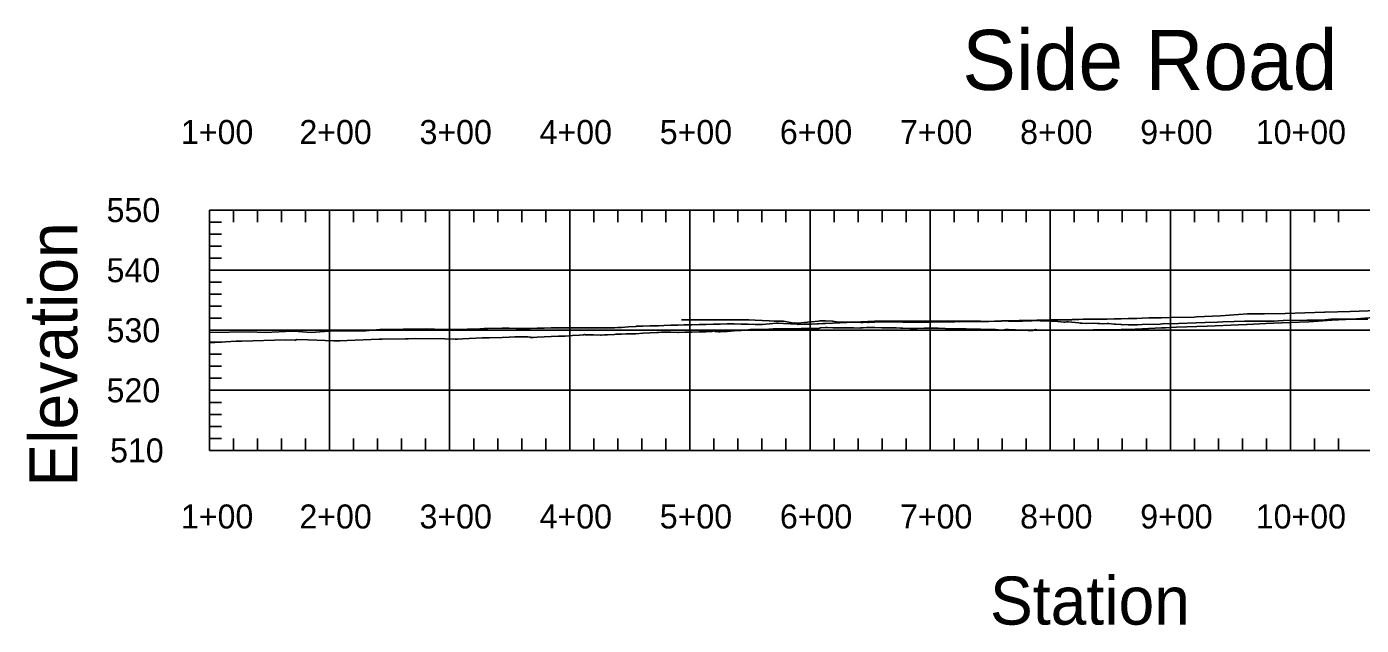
# Model space of a CAD drawing. Extents: x 704797 to 712284, y 374940 to 376945.
# Drawn here: x 708267 to 709378, y 376447 to 376945 of the extents above; entities that cross this region are included whole.
import ezdxf

# ---------------------------------------------------------------- set-up
doc = ezdxf.new("R2010")
doc.units = 0
for name, color, linetype in [('1', 7, 'Continuous'), ('61', 7, 'Continuous'), ('63', 7, 'Continuous'), ('Existing', 7, 'Continuous')]:
    doc.layers.add(name, color=color, linetype=linetype)

msp = doc.modelspace()

# ---------------------------------------------------------------- linework, layer by layer
at = {"layer": '61'}
for p, q in [((708419.5, 376792.3), (709919.5, 376792.3)), ((708419.5, 376592.3), (708419.5, 376792.3)), ((708439.5, 376792.3), (708439.5, 376782.3)), ((708459.5, 376792.3), (708459.5, 376782.3)), ((708479.5, 376792.3), (708479.5, 376782.3)), ((708499.5, 376792.3), (708499.5, 376782.3)), ((708519.5, 376592.3), (708519.5, 376792.3)), ((708539.5, 376792.3), (708539.5, 376782.3)), ((708559.5, 376792.3), (708559.5, 376782.3)), ((708579.5, 376792.3), (708579.5, 376782.3)), ((708599.5, 376792.3), (708599.5, 376782.3)), ((708619.5, 376592.3), (708619.5, 376792.3)), ((708639.5, 376792.3), (708639.5, 376782.3)), ((708659.5, 376792.3), (708659.5, 376782.3)), ((708679.5, 376792.3), (708679.5, 376782.3)), ((708699.5, 376792.3), (708699.5, 376782.3)), ((708719.5, 376592.3), (708719.5, 376792.3)), ((708739.5, 376792.3), (708739.5, 376782.3)), ((708759.5, 376792.3), (708759.5, 376782.3)), ((708779.5, 376792.3), (708779.5, 376782.3)), ((708799.5, 376792.3), (708799.5, 376782.3)), ((708819.5, 376592.3), (708819.5, 376792.3)), ((708839.5, 376792.3), (708839.5, 376782.3)), ((708859.5, 376792.3), (708859.5, 376782.3)), ((708879.5, 376792.3), (708879.5, 376782.3)), ((708899.5, 376792.3), (708899.5, 376782.3)), ((708919.5, 376592.3), (708919.5, 376792.3)), ((708939.5, 376792.3), (708939.5, 376782.3)), ((708959.5, 376792.3), (708959.5, 376782.3)), ((708979.5, 376792.3), (708979.5, 376782.3)), ((708999.5, 376792.3), (708999.5, 376782.3)), ((709019.5, 376592.3), (709019.5, 376792.3)), ((709039.5, 376792.3), (709039.5, 376782.3)), ((709059.5, 376792.3), (709059.5, 376782.3)), ((709079.5, 376792.3), (709079.5, 376782.3)), ((709099.5, 376792.3), (709099.5, 376782.3)), ((709119.5, 376592.3), (709119.5, 376792.3)), ((709139.5, 376792.3), (709139.5, 376782.3)), ((709159.5, 376792.3), (709159.5, 376782.3)), ((709179.5, 376792.3), (709179.5, 376782.3)), ((709199.5, 376792.3), (709199.5, 376782.3)), ((709219.5, 376592.3), (709219.5, 376792.3)), ((709239.5, 376792.3), (709239.5, 376782.3)), ((709259.5, 376792.3), (709259.5, 376782.3)), ((709279.5, 376792.3), (709279.5, 376782.3)), ((709299.5, 376792.3), (709299.5, 376782.3)), ((709319.5, 376592.3), (709319.5, 376792.3)), ((709339.5, 376792.3), (709339.5, 376782.3)), ((709359.5, 376792.3), (709359.5, 376782.3)), ((708419.5, 376782.3), (708429.5, 376782.3)), ((708419.5, 376772.3), (708429.5, 376772.3)), ((708419.5, 376762.3), (708429.5, 376762.3)), ((708419.5, 376752.3), (708429.5, 376752.3)), ((708419.5, 376742.3), (709919.5, 376742.3)), ((708419.5, 376732.3), (708429.5, 376732.3)), ((708419.5, 376722.3), (708429.5, 376722.3)), ((708419.5, 376712.3), (708429.5, 376712.3)), ((708419.5, 376702.3), (708429.5, 376702.3)), ((708419.5, 376692.3), (709919.5, 376692.3)), ((708419.5, 376682.3), (708429.5, 376682.3)), ((708419.5, 376672.3), (708429.5, 376672.3)), ((708419.5, 376662.3), (708429.5, 376662.3)), ((708419.5, 376652.3), (708429.5, 376652.3)), ((708419.5, 376642.3), (709919.5, 376642.3)), ((708419.5, 376632.3), (708429.5, 376632.3)), ((708419.5, 376622.3), (708429.5, 376622.3)), ((708419.5, 376612.3), (708429.5, 376612.3)), ((708419.5, 376602.3), (708429.5, 376602.3)), ((708439.5, 376592.3), (708439.5, 376602.3)), ((708459.5, 376592.3), (708459.5, 376602.3)), ((708479.5, 376592.3), (708479.5, 376602.3)), ((708499.5, 376592.3), (708499.5, 376602.3)), ((708539.5, 376592.3), (708539.5, 376602.3)), ((708559.5, 376592.3), (708559.5, 376602.3)), ((708579.5, 376592.3), (708579.5, 376602.3)), ((708599.5, 376592.3), (708599.5, 376602.3)), ((708639.5, 376592.3), (708639.5, 376602.3)), ((708659.5, 376592.3), (708659.5, 376602.3)), ((708679.5, 376592.3), (708679.5, 376602.3)), ((708699.5, 376592.3), (708699.5, 376602.3)), ((708739.5, 376592.3), (708739.5, 376602.3)), ((708759.5, 376592.3), (708759.5, 376602.3)), ((708779.5, 376592.3), (708779.5, 376602.3)), ((708799.5, 376592.3), (708799.5, 376602.3)), ((708839.5, 376592.3), (708839.5, 376602.3)), ((708859.5, 376592.3), (708859.5, 376602.3)), ((708879.5, 376592.3), (708879.5, 376602.3)), ((708899.5, 376592.3), (708899.5, 376602.3)), ((708939.5, 376592.3), (708939.5, 376602.3)), ((708959.5, 376592.3), (708959.5, 376602.3)), ((708979.5, 376592.3), (708979.5, 376602.3)), ((708999.5, 376592.3), (708999.5, 376602.3)), ((709039.5, 376592.3), (709039.5, 376602.3)), ((709059.5, 376592.3), (709059.5, 376602.3)), ((709079.5, 376592.3), (709079.5, 376602.3)), ((709099.5, 376592.3), (709099.5, 376602.3)), ((709139.5, 376592.3), (709139.5, 376602.3)), ((709159.5, 376592.3), (709159.5, 376602.3)), ((709179.5, 376592.3), (709179.5, 376602.3)), ((709199.5, 376592.3), (709199.5, 376602.3)), ((709239.5, 376592.3), (709239.5, 376602.3)), ((709259.5, 376592.3), (709259.5, 376602.3)), ((709279.5, 376592.3), (709279.5, 376602.3)), ((709299.5, 376592.3), (709299.5, 376602.3)), ((709339.5, 376592.3), (709339.5, 376602.3)), ((709359.5, 376592.3), (709359.5, 376602.3)), ((708419.5, 376592.3), (709919.5, 376592.3))]:
    msp.add_line(p, q, dxfattribs=at)
at = {"layer": '63'}
for points in [[(708419.5, 376681.8), (708441.7, 376683.2), (708444.7, 376683.3), (708446.6, 376683.3), (708482.9, 376684.3), (708490.6, 376684), (708491.3, 376684), (708492.4, 376684.5), (708501.7, 376684.2), (708523.2, 376683.4), (708526.3, 376683.4), (708528.1, 376683.5), (708534.3, 376683.9), (708560.7, 376685), (708563.2, 376684.9), (708582.7, 376685.3), (708585.1, 376685.3), (708591, 376685.5), (708615.6, 376685.3), (708624, 376684.9), (708626.1, 376685), (708630.5, 376685.3), (708646.6, 376686), (708649.2, 376686), (708650.8, 376686), (708652.5, 376686), (708663.1, 376686.4), (708669, 376686.5), (708673.8, 376686.7), (708674.8, 376686.7), (708680.7, 376686.8), (708684.5, 376686.8), (708686.5, 376686.5), (708687, 376686.4), (708689, 376686.4), (708692.4, 376686.6), (708698.2, 376686.9), (708704.1, 376687.2), (708710, 376687.5), (708710.2, 376687.5), (708715.1, 376687.4), (708715.8, 376687.5), (708721.7, 376687.9), (708727.5, 376688.3), (708730.6, 376688.5), (708731.3, 376688.5), (708731.7, 376688.8), (708732.6, 376688.6), (708733.4, 376688.6), (708739.2, 376688.4), (708745.1, 376688.3), (708745.8, 376688.3), (708748.4, 376688.4), (708751, 376688.6), (708756.8, 376688.9), (708757.9, 376689), (708762.7, 376689.1), (708766.5, 376689.3), (708768.5, 376689.3), (708772.5, 376689.3), (708774.4, 376689.4), (708780.2, 376689.8), (708786.1, 376690.1), (708791.9, 376690.4), (708793.4, 376690.5), (708795.8, 376690.6), (708796.1, 376690.8), (708797.4, 376690.7), (708797.8, 376690.7), (708803.7, 376690.6), (708809.5, 376690.5), (708809.9, 376690.5), (708815.4, 376690.7), (708815.4, 376690.7), (708821.2, 376690.8), (708827.1, 376691), (708832.9, 376691.1), (708835.5, 376691.2), (708837.9, 376691.2), (708838.8, 376691.5), (708839.6, 376691.7), (708840.6, 376691.3), (708843.4, 376691.1), (708844.7, 376691.1), (708849, 376691.2), (708850.5, 376691.3), (708856.4, 376691.8), (708862.2, 376692.2), (708868.1, 376692.7), (708869.7, 376692.8), (708873.9, 376692.9), (708875.6, 376692.9), (708879.8, 376693), (708881.1, 376693), (708885.2, 376693.3), (708885.7, 376693.3), (708888.8, 376693.4), (708891.5, 376693.4), (708897.4, 376693.4), (708901, 376693.4), (708903.2, 376693.5), (708906.5, 376693.6), (708909.1, 376693.6), (708912, 376693.7), (708914.9, 376693.7), (708920.8, 376693.7), (708925.2, 376693.7), (708926.7, 376693.9), (708928.1, 376694.2), (708932.5, 376694.5), (708933.7, 376694.5), (708938.4, 376694.3), (708941.8, 376694.2), (708944.2, 376694.3), (708946.1, 376694.3), (708950.1, 376694.3), (708955.9, 376694.2), (708961.1, 376694.1), (708961.8, 376694.2), (708963.8, 376694.2), (708966.7, 376694.5), (708967.7, 376694.5), (708971.6, 376694.5), (708973.5, 376694.5), (708979.4, 376694.4), (708985.2, 376694.3), (708991.1, 376694.2), (708994.7, 376694.1), (708996.9, 376694.1), (709002.8, 376693.9), (709004.2, 376693.9), (709004.6, 376693.8), (709005, 376693.9), (709008.6, 376693.9), (709014.5, 376694), (709020.4, 376694), (709025.8, 376694), (709026.2, 376694), (709032.1, 376693.8), (709037.9, 376693.6), (709041.3, 376693.5), (709042.1, 376693.5), (709042.8, 376693.5), (709043.4, 376693.5), (709043.8, 376693.5), (709049.6, 376693.4), (709055.5, 376693.3), (709061.4, 376693.2), (709067.2, 376693), (709073.1, 376692.9), (709073.9, 376692.8), (709078.9, 376692.4), (709079.3, 376692.4), (709082.3, 376692.9), (709084.8, 376692.8), (709090.6, 376692.6), (709096.5, 376692.3), (709101.1, 376692.1), (709102.4, 376692.1), (709104.8, 376692.2), (709107.2, 376692.9), (709108.2, 376692.7), (709110.2, 376692.3), (709112.8, 376692.4), (709114.1, 376692.4), (709119.9, 376692.4), (709125.8, 376692.4), (709131.6, 376692.3), (709137.5, 376692.3), (709138.3, 376692.3), (709140, 376692.3), (709143.4, 376692.4), (709144.5, 376692.4), (709149.2, 376692.5), (709155.1, 376692.6), (709160.9, 376692.7), (709166.8, 376692.7), (709172.6, 376692.7), (709176.8, 376692.7), (709178.5, 376692.8), (709181.8, 376692.8), (709184.4, 376692.8), (709185, 376692.8), (709190.2, 376693.1), (709196.1, 376693.4), (709212.1, 376694.3), (709215.4, 376694.4), (709224.5, 376694.8), (709250, 376695.7), (709263.4, 376696.2), (709282.5, 376697.2), (709283.4, 376697.2), (709299, 376698), (709319, 376698.7), (709334.8, 376699.2), (709354, 376700.8), (709370.9, 376701.4), (709388.7, 376702.9)], [(708812.5, 376701), (708815.4, 376701), (708821.2, 376701), (708827.1, 376701), (708832.9, 376700.9), (708838.8, 376700.9), (708843, 376700.9), (708844.7, 376700.9), (708850.5, 376701.1), (708851.8, 376701.1), (708856.4, 376701.1), (708862.2, 376701), (708868.1, 376701), (708868.7, 376701), (708873.9, 376700.7), (708879.8, 376700.5), (708885.4, 376700.2), (708885.7, 376700.2), (708889.6, 376700), (708891.5, 376700), (708897.4, 376699.9), (708897.4, 376699.9), (708903.2, 376698.7), (708906.3, 376698.1), (708906.7, 376698.5), (708907.4, 376698.1), (708909.1, 376698.2), (708914.9, 376698.8), (708917.4, 376699), (708920.8, 376699.4), (708926.7, 376700), (708927.8, 376700.1), (708932.5, 376700.1), (708938.1, 376700), (708938.4, 376700), (708942.8, 376698.9), (708944.2, 376698.9), (708950.1, 376699), (708955.9, 376699), (708957.2, 376699), (708961.8, 376698.8), (708963.6, 376698.7), (708965.3, 376699), (708967.7, 376698.8), (708968.2, 376698.8), (708973.5, 376699), (708979.4, 376699.2), (708985, 376699.4), (708985.2, 376699.4), (708991.1, 376699.3), (708996.9, 376699.1), (709002.8, 376699), (709004.8, 376699), (709005.8, 376699), (709006.6, 376699), (709008.6, 376699), (709014.5, 376699.1), (709020.4, 376699.1), (709026.2, 376699.2), (709032.1, 376699.3), (709037.9, 376699.4), (709038.2, 376699.4), (709040.2, 376699.4), (709042.5, 376699.6), (709043.8, 376699.5), (709044, 376699.4), (709045.9, 376699.5), (709049.6, 376699.5), (709055.5, 376699.6), (709061.4, 376699.6), (709067.2, 376699.7), (709073.1, 376699.8), (709074.2, 376699.8), (709078.4, 376699.9), (709078.9, 376699.9), (709082.4, 376700.1), (709084.8, 376700), (709087.3, 376700), (709090.6, 376700), (709096.5, 376700), (709102.4, 376700.1), (709104.5, 376700.1), (709107.9, 376700.3), (709108.2, 376700.3), (709111, 376700.2), (709114.1, 376700.1), (709118.9, 376700), (709119.9, 376699.9), (709125.8, 376699.5), (709130.7, 376699.1), (709131.6, 376699.1), (709131.9, 376699.1), (709133, 376699.3), (709134.3, 376699.2), (709137.5, 376698.9), (709143.4, 376698.4), (709144.3, 376698.3), (709145.9, 376698.2), (709149.2, 376698), (709149.5, 376698), (709155.1, 376698.1), (709155.3, 376698.1), (709158.9, 376697.9), (709160.9, 376697.8), (709162.8, 376697.6), (709166.8, 376697.8), (709167.9, 376697.9), (709172.6, 376697.5), (709173, 376697.5), (709173.7, 376697.4), (709178.5, 376697), (709179.3, 376696.9), (709183.1, 376697), (709184.4, 376696.9), (709187.2, 376696.7), (709190.2, 376696.8), (709192, 376696.9), (709196.1, 376697), (709211.1, 376697.3), (709215, 376697.8), (709218.9, 376697.6), (709248.5, 376698.7), (709258.8, 376699.1), (709263.1, 376699.2), (709272.6, 376699.6), (709281.3, 376699.8), (709287.4, 376699.8), (709305.6, 376700), (709313.3, 376700.4), (709333, 376700.6), (709345.7, 376700.8), (709353, 376701.4), (709383.9, 376701.4)]]:
    msp.add_lwpolyline(points, dxfattribs=at)
at = {"layer": 'Existing'}
msp.add_lwpolyline([(708419.5, 376690.4), (708452.7, 376690.9), (708452.7, 376690.9), (708466, 376690.4), (708488.6, 376691.6), (708489.7, 376691.6), (708504.1, 376690.5), (708522.5, 376691.8), (708523, 376691.8), (708549.8, 376691.8), (708561.5, 376692.8), (708600, 376693.4), (708614.2, 376692.8), (708623.2, 376693), (708644.7, 376693.6), (708648.3, 376693.8), (708651.3, 376693.8), (708663.1, 376694), (708663.2, 376694), (708669, 376694), (708674.8, 376693.9), (708680.4, 376693.9), (708680.7, 376693.9), (708682.8, 376693.8), (708684.3, 376693.8), (708685.8, 376693.8), (708686.5, 376693.8), (708692.4, 376694), (708698.2, 376694.1), (708704.1, 376694.3), (708706.5, 376694.3), (708710, 376694.3), (708715.6, 376694.2), (708715.8, 376694.2), (708721.7, 376694.3), (708726.2, 376694.4), (708727.5, 376694.4), (708727.6, 376694.4), (708729, 376694.4), (708730.4, 376694.4), (708733.4, 376694.4), (708739.2, 376694.3), (708745.1, 376694.2), (708750.9, 376694.2), (708751, 376694.2), (708754.8, 376694.3), (708756.8, 376694.4), (708759.6, 376694.5), (708762.7, 376694.7), (708768.5, 376695.1), (708774.4, 376695.5), (708775.1, 376695.6), (708775.3, 376695.6), (708776.9, 376695.6), (708780.2, 376695.8), (708786.1, 376695.9), (708791.9, 376696.1), (708793.5, 376696.1), (708797.8, 376696.3), (708803.7, 376696.4), (708809.5, 376696.6), (708814.4, 376696.7), (708815.4, 376696.7), (708815.5, 376696.7), (708816.6, 376696.7), (708817.5, 376696.7), (708821.2, 376696.9), (708827.1, 376697), (708832.9, 376697.2), (708838.8, 376697.4), (708843.4, 376697.5), (708844.7, 376697.5), (708850.5, 376697.6), (708851.2, 376697.6), (708851.7, 376697.6), (708856.4, 376697.6), (708862.2, 376697.4), (708868.1, 376697.3), (708873.9, 376697.2), (708878.9, 376697.1), (708879.8, 376697.1), (708885.7, 376697.6), (708891.5, 376698.1), (708892.1, 376698.1), (708892.4, 376698.1), (708892.6, 376698.1), (708892.9, 376698.1), (708897.4, 376697.9), (708903.2, 376697.6), (708909.1, 376697.3), (708909.7, 376697.2), (708914.9, 376697.3), (708915.3, 376697.4), (708920.4, 376697.5), (708920.8, 376697.5), (708925.4, 376697.7), (708926.7, 376697.7), (708930.1, 376697.8), (708932.5, 376697.9), (708938.4, 376698.2), (708944.2, 376698.5), (708950.1, 376698.8), (708955.9, 376699), (708961.8, 376699.3), (708967.7, 376699.6), (708969.1, 376699.6), (708972.6, 376699.7), (708973.5, 376699.8), (708975.1, 376699.8), (708979.4, 376699.9), (708983.4, 376700), (708985.2, 376700), (708988.5, 376700), (708991.1, 376700), (708996.9, 376700), (709002.8, 376700), (709008.6, 376700), (709014.5, 376700), (709016.8, 376700), (709020.4, 376700), (709026.2, 376699.9), (709026.5, 376699.9), (709032.1, 376700), (709033.1, 376700), (709034, 376700), (709034.9, 376700), (709035.8, 376700), (709037.9, 376700), (709043.8, 376700), (709046.4, 376699.9), (709049.6, 376699.9), (709051.3, 376699.8), (709055.5, 376699.9), (709056.5, 376699.9), (709061.4, 376699.8), (709066, 376699.7), (709067.2, 376699.7), (709067.2, 376699.7), (709068.5, 376699.7), (709073.1, 376699.9), (709078.9, 376700.1), (709080.8, 376700.1), (709084.8, 376700.2), (709085.7, 376700.2), (709090.6, 376700.2), (709093.6, 376700.3), (709096.5, 376700.3), (709098.2, 376700.3), (709102.4, 376700.4), (709108.2, 376700.6), (709114.1, 376700.8), (709115, 376700.8), (709116.2, 376700.8), (709117, 376700.8), (709117.8, 376700.8), (709119.9, 376700.9), (709125.8, 376700.9), (709128.9, 376701), (709131.6, 376701), (709137.5, 376701.1), (709137.7, 376701.2), (709143.4, 376701.3), (709146.9, 376701.4), (709149.2, 376701.4), (709155.1, 376701.4), (709160.8, 376701.4), (709160.9, 376701.4), (709162.3, 376701.4), (709164, 376701.4), (709166.8, 376701.5), (709172.6, 376701.7), (709178.4, 376701.9), (709178.5, 376701.9), (709184.4, 376702), (709185.2, 376702), (709190.2, 376702.1), (709191.6, 376702.1), (709196.1, 376702.4), (709201.5, 376702.7), (709201.6, 376702.7), (709201.7, 376702.7), (709212.1, 376702.6), (709219.3, 376702.8), (709239.3, 376703.3), (709241.2, 376703.4), (709261.1, 376704.4), (709283.6, 376706), (709297.9, 376706), (709315, 376706.3), (709347.9, 376707.4), (709348.1, 376707.4), (709348.3, 376707.4), (709369.1, 376707.8), (709399.2, 376708.9)], dxfattribs=at)

# ---------------------------------------------------------------- texts
at = {"layer": '1'}
for s, height, p in [('Side Road', 50, (709046.3, 376892.3)), ('Station', 40, (709069.3, 376447.3))]:
    msp.add_text(s, height=height, dxfattribs=at).set_placement(p)
msp.add_text('Elevation', height=40, rotation=90, dxfattribs=at).set_placement((708309.5, 376562.1))
at = {"layer": '61'}
for s, p in [('1+00', (708395.8, 376847.3)), ('2+00', (708494.4, 376847.3)), ('3+00', (708594.4, 376847.3)), ('4+00', (708694.4, 376847.3)), ('5+00', (708794.4, 376847.3)), ('6+00', (708894.4, 376847.3)), ('7+00', (708994.4, 376847.3)), ('8+00', (709094.4, 376847.3)), ('9+00', (709194.4, 376847.3)), ('10+00', (709290.6, 376847.3)), ('550', (708333.9, 376782.3)), ('550', (708333.9, 376782.3)), ('540', (708333.9, 376732.3)), ('530', (708333.9, 376682.3)), ('520', (708333.9, 376632.3)), ('510', (708336.8, 376582.3)), ('1+00', (708395.8, 376527.3)), ('2+00', (708494.4, 376527.3)), ('3+00', (708594.4, 376527.3)), ('4+00', (708694.4, 376527.3)), ('5+00', (708794.4, 376527.3)), ('6+00', (708894.4, 376527.3)), ('7+00', (708994.4, 376527.3)), ('8+00', (709094.4, 376527.3)), ('9+00', (709194.4, 376527.3)), ('10+00', (709290.6, 376527.3))]:
    msp.add_text(s, height=20, dxfattribs=at).set_placement(p)

doc.saveas('drawing.dxf')
